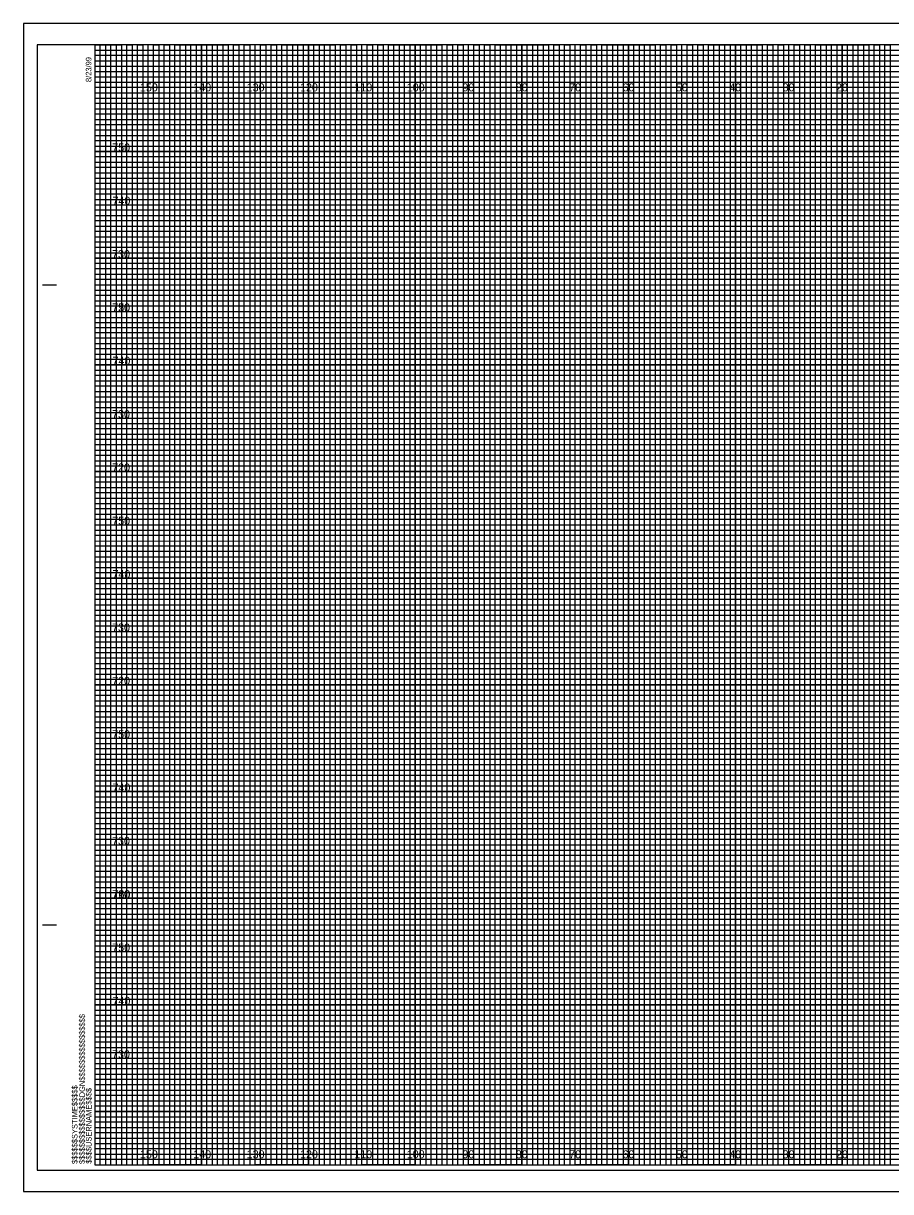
# Model space of a CAD drawing. Extents: x -13 to 323, y -5 to 214.
# Drawn here: x -13.4 to 149.1, y -5 to 214 of the extents above; entities that cross this region are included whole.
import ezdxf

# ---------------------------------------------------------------- set-up
doc = ezdxf.new("R2010")
doc.units = 0
for name, color, linetype in [('Prop XS Elevation Labels', 7, 'Continuous'), ('Prop XS Offset Labels', 7, 'Continuous'), ('Sheet Cross Section CELL', 7, 'Continuous'), ('Sheet Cross Section Grid Major CELL', 7, 'Continuous'), ('Sheet Cross Section Grid Middle CELL', 7, 'Continuous'), ('Sheet Cross Section Grid Minor 1 CELL', 7, 'Continuous'), ('Sheet Cross Section Grid Minor 2 CELL', 7, 'Continuous'), ('Sheet Cutting Line CELL', 7, 'Continuous'), ('Sheet DOT Grid CELL', 7, 'Continuous'), ('Sheet Plot Border Inside CELL', 7, 'Continuous'), ('Sheet Plot Border Outside CELL', 7, 'Continuous')]:
    doc.layers.add(name, color=color, linetype=linetype)

msp = doc.modelspace()

# ---------------------------------------------------------------- linework, layer by layer
at = {"layer": 'Sheet Cross Section CELL'}
for p, q in [((-9.8, 165), (-7.3, 165)), ((-9.7, 165), (-7.2, 165)), ((-9.8, 45), (-7.3, 45)), ((-9.7, 45), (-7.2, 45)), ((0, 0), (0, 0)), ((0, 0), (0, 0)), ((0, 0), (0, 0)), ((0, 0), (0, 0)), ((0, 0), (0, 0)), ((0, 0), (0, 0)), ((0, 0), (0, 0))]:
    msp.add_line(p, q, dxfattribs=at)
msp.add_lwpolyline([(320, 210), (0, 210), (0, 0), (320, 0)], close=True, dxfattribs=at)
at = {"layer": 'Sheet Cross Section Grid Major CELL'}
for p, q in [((10, 210), (0, 210)), ((10, 0), (10, 210)), ((30, 210), (20, 210)), ((20, 210), (20, 0)), ((30, 0), (30, 210)), ((50, 210), (40, 210)), ((40, 210), (40, 0)), ((50, 0), (50, 210)), ((70, 210), (60, 210)), ((60, 210), (60, 0)), ((70, 0), (70, 210)), ((90, 210), (80, 210)), ((80, 210), (80, 0)), ((90, 0), (90, 210)), ((110, 210), (100, 210)), ((100, 210), (100, 0)), ((110, 0), (110, 210)), ((130, 210), (120, 210)), ((120, 210), (120, 0)), ((130, 0), (130, 210)), ((150, 210), (140, 210)), ((140, 210), (140, 0)), ((20, 0), (10, 0)), ((40, 0), (30, 0)), ((60, 0), (50, 0)), ((80, 0), (70, 0)), ((100, 0), (90, 0)), ((120, 0), (110, 0)), ((140, 0), (130, 0))]:
    msp.add_line(p, q, dxfattribs=at)
for points in [[(0, 200), (320, 200), (320, 190), (0, 190)], [(0, 180), (320, 180), (320, 170), (0, 170)], [(0, 160), (320, 160), (320, 150), (0, 150)], [(0, 140), (320, 140), (320, 130), (0, 130)], [(0, 120), (320, 120), (320, 110), (0, 110)], [(0, 100), (320, 100), (320, 90), (0, 90)], [(0, 80), (320, 80), (320, 70), (0, 70)], [(0, 60), (320, 60), (320, 50), (0, 50)], [(0, 40), (320, 40), (320, 30), (0, 30)], [(0, 20), (320, 20), (320, 10), (0, 10)]]:
    msp.add_lwpolyline(points, dxfattribs=at)
at = {"layer": 'Sheet Cross Section Grid Middle CELL'}
for points in [[(0, 210), (5, 210), (5, 0), (15, 0), (15, 210), (25, 210), (25, 0), (35, 0), (35, 210), (45, 210), (45, 0), (55, 0), (55, 210), (65, 210), (65, 0), (75, 0), (75, 210), (85, 210), (85, 0), (95, 0), (95, 210), (105, 210), (105, 0), (115, 0), (115, 210), (125, 210), (125, 0), (135, 0), (135, 210), (145, 210), (145, 0), (155, 0)], [(0, 205), (275, 205)], [(0, 185), (320, 185), (320, 195), (0, 195)], [(0, 165), (320, 165), (320, 175), (0, 175)], [(0, 145), (320, 145), (320, 155), (0, 155)], [(0, 125), (320, 125), (320, 135), (0, 135)], [(0, 105), (320, 105), (320, 115), (0, 115)], [(0, 85), (320, 85), (320, 95), (0, 95)], [(0, 65), (320, 65), (320, 75), (0, 75)], [(0, 45), (320, 45), (320, 55), (0, 55)], [(0, 25), (320, 25), (320, 35), (0, 35)], [(0, 5), (320, 5), (320, 15), (0, 15)]]:
    msp.add_lwpolyline(points, dxfattribs=at)
at = {"layer": 'Sheet Cross Section Grid Minor 1 CELL'}
for p, q in [((0, 209), (260, 209)), ((260, 207.98), (0, 207.98)), ((0, 207.98), (0, 207)), ((0, 207), (260, 207)), ((260, 205.89), (0, 205.89)), ((0, 205.89), (0, 204)), ((0, 204), (320, 204))]:
    msp.add_line(p, q, dxfattribs=at)
for points in [[(0, 203), (270, 203), (320, 203), (320, 202), (0, 202)], [(0, 201), (320, 201), (320, 199), (0, 199)], [(0, 198), (320, 198), (320, 197), (0, 196.98)], [(0, 196), (320, 196), (320, 194), (0, 194)], [(0, 193), (320, 193), (320, 192), (0, 192)], [(0, 191), (320, 191), (320, 189), (0, 189)], [(0, 188), (320, 188), (320, 187), (0, 187)], [(0, 186), (320, 186), (320, 184), (0, 184)], [(0, 183), (320, 183), (320, 182), (0, 182)], [(0, 181), (320, 181), (320, 179), (0, 179)], [(0, 178), (320, 178), (320, 177), (0, 177)], [(0, 176), (320, 176), (320, 173.95), (320, 173), (320, 172), (0, 172)], [(0, 174), (320, 174), (320, 173), (0, 173)], [(0, 171), (320, 171), (320, 169), (0, 169.03)], [(0, 169.03), (320, 169), (320, 168), (0, 168)], [(0, 167), (320, 167), (320, 166), (0, 166)], [(0, 164), (320, 164), (320, 163), (0, 163)], [(0, 162), (320, 162), (320, 161), (0, 161)], [(-0.07, 158.89), (320, 158.89), (320, 157.88), (-0.07, 157.88)], [(0, 157), (320, 157), (320, 156), (0, 156)], [(0, 154), (320, 154), (320, 153), (0, 153)], [(0, 152), (320, 152), (320, 151), (0, 151)], [(0, 149), (320, 149), (320, 148), (0, 148)], [(0, 147), (320, 147), (320, 146), (0, 146)], [(0, 144), (320, 144), (320, 143), (0, 143)], [(0, 142), (320, 142), (320, 141), (0, 141)], [(0, 139), (320, 139), (319.99, 137.98), (0, 138)], [(0, 137), (320, 137), (320, 136), (0, 136)], [(0, 134), (320, 134), (320, 133), (0, 133)], [(0, 132), (320, 132), (320, 131), (0, 131)], [(0, 129), (320, 129), (320, 128), (0, 128)], [(0, 127), (320, 127), (320, 126), (0, 126)], [(0, 124), (320, 124), (320, 123), (0, 123)], [(0, 122), (320, 122), (320, 121), (0, 121)], [(0, 119), (320, 119), (320, 118), (0, 118)], [(0, 116.99), (320.07, 116.91), (320, 116), (0, 116)], [(0, 114), (320, 114), (320, 113), (0, 113)], [(0, 112), (320, 112), (320, 111), (0, 111)], [(0, 109), (320, 109), (320, 108), (0, 108)], [(0, 107), (320, 107), (320, 106), (0, 106)], [(0, 104), (320, 104), (320, 103), (0, 103)], [(0, 102), (320, 102), (320, 101), (0, 101)], [(0, 99), (320, 99), (320, 98), (0, 98)], [(0, 97), (320, 97), (320, 96), (0, 96)], [(0, 94), (320, 94), (320, 93), (0, 93)], [(0, 92), (320, 92), (320, 91), (0, 91)], [(0, 89), (320, 89), (320, 88), (0, 88)], [(0, 87), (320, 87), (320, 86), (0, 86)], [(0, 84), (320, 84), (320, 83), (0, 83)], [(0, 82), (320, 82), (320, 81), (0, 81)], [(0, 79), (320, 79), (319.99, 77.98), (0, 78)], [(0, 77), (320, 77), (320, 76), (0, 76)], [(0, 74), (320, 74), (320, 73), (0, 73)], [(0, 72), (320, 72), (320, 71), (0, 71)], [(0, 69), (320, 69), (320, 68), (0, 68)], [(0, 67), (320, 67), (320, 66), (0, 66)], [(0, 64), (320, 64), (320, 63), (0, 63)], [(0, 62), (320, 62), (320, 61), (0, 61)], [(0, 59), (320, 59), (320, 58), (0, 58)], [(0, 56.99), (320.07, 56.91), (320, 56), (0, 56)], [(0, 54), (320, 54), (320, 53), (0, 53)], [(0, 52), (320, 52), (320, 51), (0, 51)], [(0, 49), (320, 49), (320, 48), (0, 48)], [(0, 47), (320, 47), (320, 46), (0, 46)], [(0, 44), (320, 44), (320, 43), (0, 43)], [(0, 42), (320, 42), (320, 41), (0, 41)], [(0, 39), (320, 39), (320, 38), (0, 38)], [(0, 37), (320, 37), (320, 36), (0, 36)], [(0, 34), (320, 34), (320, 33), (0, 33)], [(0, 32), (320, 32), (320, 31), (0, 31)], [(0, 29), (320, 29), (320, 28), (0, 28)], [(0, 27), (320, 27), (320, 26), (0, 26)], [(0, 24), (320, 24), (320, 23), (0, 23)], [(0, 22), (320, 22), (320, 21), (0, 21)], [(0, 19), (320, 19), (320, 18), (0, 18)], [(0, 17), (320, 17), (320, 16), (0, 16)], [(0, 14), (320, 14), (320, 13), (0, 13)], [(0, 12), (320, 12), (320, 11), (0, 11)], [(0, 9), (320, 9), (320, 8), (0, 8)], [(0, 7), (320, 7), (320, 6), (0, 6)], [(0, 4), (320, 4), (320, 3), (0, 3)], [(0, 2), (320, 2), (320, 1), (0, 1)]]:
    msp.add_lwpolyline(points, dxfattribs=at)
at = {"layer": 'Sheet Cross Section Grid Minor 2 CELL'}
for points in [[(0, 0), (1, 0), (1, 210), (2, 210), (2, 0)], [(2, 0), (3, 0), (3, 210), (4, 210), (4, 0)], [(5, 0), (6, 0), (6, 210), (7, 210), (7, 0)], [(7, 0), (8, 0), (8, 210), (9, 210), (9, 0)], [(10, 0), (11, 0), (11, 210), (12, 210), (12, 0)], [(12, 0), (13, 0), (13, 210), (14, 210), (14, 0)], [(15, 0), (16, 0), (16, 210), (17, 210), (17, 0)], [(17, 0), (18, 0), (18, 210), (19, 210), (19, 0)], [(20, 0), (21, 0), (21, 210), (22, 210), (22, 0)], [(22, 0), (23, 0), (23, 210), (24, 210), (24, 0)], [(25, 0), (26, 0), (26, 210), (27, 210), (27, 0)], [(27, 0), (28, 0), (28, 210), (29, 210), (29, 0)], [(30, 0), (31, 0), (31, 210), (32, 210), (32, 0)], [(32, 0), (33, 0), (33, 210), (34, 210), (34, 0)], [(35, 0), (36, 0), (36, 210), (37, 210), (37, 0)], [(37, 0), (38, 0), (38, 210), (39, 210), (39, 0)], [(40, 0), (41, 0), (41, 210), (42, 210), (42, 0)], [(42, 0), (43, 0), (43, 210), (44, 210), (44, 0)], [(45, 0), (46, 0), (46, 210), (47, 210), (47, 0)], [(47, 0), (48, 0), (48, 210), (49, 210), (49, 0)], [(50, 0), (51, 0), (51, 210), (52, 210), (52, 0)], [(52, 0), (53, 0), (53, 210), (54, 210), (54, 0)], [(55, 0), (56, 0), (56, 210), (57, 210), (57, 0)], [(57, 0), (58, 0), (58, 210), (59, 210), (59, 0)], [(60, 0), (61, 0), (61, 210), (62, 210), (62, 0)], [(62, 0), (63, 0), (63, 210), (64, 210), (64, 0)], [(65, 0), (66, 0), (66, 210), (67, 210), (67, 0)], [(67, 0), (68, 0), (68, 210), (69, 210), (69, 0)], [(70, 0), (71, 0), (71, 210), (72, 210), (72, 0)], [(72, 0), (73, 0), (73, 210), (74, 210), (74, 0)], [(75, 0), (76, 0), (76, 210), (77, 210), (77, 0)], [(77, 0), (78, 0), (78, 210), (79, 210), (79, 0)], [(80, 0), (81, 0), (81, 210), (82, 210), (82, 0)], [(82, 0), (83, 0), (83, 210), (84, 210), (84, 0)], [(85, 0), (86, 0), (86, 210), (87, 210), (87, 0)], [(87, 0), (88, 0), (88, 210), (89, 210), (89, 0)], [(90, 0), (91, 0), (91, 210), (92, 210), (92, 0)], [(92, 0), (93, 0), (93, 210), (94, 210), (94, 0)], [(95, 0), (96, 0), (96, 210), (97, 210), (97, 0)], [(97, 0), (98, 0), (98, 210), (99, 210), (99, 0)], [(100, 0), (101, 0), (101, 210), (102, 210), (102, 0)], [(102, 0), (103, 0), (103, 210), (104, 210), (104, 0)], [(105, 0), (106, 0), (106, 210), (107, 210), (107, 0)], [(107, 0), (108, 0), (108, 210), (109, 210), (109, 0)], [(110, 0), (111, 0), (111, 210), (112, 210), (112, 0)], [(112, 0), (113, 0), (113, 210), (114, 210), (114, 0)], [(115, 0), (116, 0), (116, 210), (117, 210), (117, 0)], [(117, 0), (118, 0), (118, 210), (119, 210), (119, 0)], [(120, 0), (121, 0), (121, 210), (122, 210), (122, 0)], [(122, 0), (123, 0), (123, 210), (124, 210), (124, 0)], [(125, 0), (126, 0), (126, 210), (127, 210), (127, 0)], [(127, 0), (128, 0), (128, 210), (129, 210), (129, 0)], [(130, 0), (131, 0), (131, 210), (132, 210), (132, 0)], [(132, 0), (133, 0), (133, 210), (134, 210), (134, 0)], [(135, 0), (136, 0), (136, 210), (137, 210), (137, 0)], [(137, 0), (138, 0), (138, 210), (139, 210), (139, 0)], [(140, 0), (141, 0), (141, 210), (142, 210), (142, 0)], [(142, 0), (143, 0), (143, 210), (144, 210), (144, 0)], [(145, 0), (146, 0), (146, 210), (147, 210), (147, 0)], [(147, 0), (148, 0), (148, 210), (149, 210), (149, 0)]]:
    msp.add_lwpolyline(points, dxfattribs=at)
at = {"layer": 'Sheet Cutting Line CELL'}
for p, q in [((323.3, 214), (-13.4, 214)), ((-13.4, 214), (-13.4, -5)), ((-13.4, -5), (323.3, -5))]:
    msp.add_line(p, q, dxfattribs=at)
at = {"layer": 'Sheet DOT Grid CELL'}
for p, q in [((10, 0), (10, 210)), ((20, 0), (20, 210)), ((30, 0), (30, 210)), ((40, 0), (40, 210)), ((50, 0), (50, 210)), ((60, 0), (60, 210)), ((70, 0), (70, 210)), ((80, 0), (80, 210)), ((90, 0), (90, 210)), ((100, 0), (100, 210)), ((110, 0), (110, 210)), ((120, 0), (120, 210)), ((130, 0), (130, 210)), ((140, 0), (140, 210)), ((0, 200), (320, 200)), ((0, 190), (320, 190)), ((0, 180), (320, 180)), ((0, 170), (320, 170)), ((0, 160), (320, 160)), ((0, 150), (320, 150)), ((0, 140), (320, 140)), ((0, 130), (320, 130)), ((0, 120), (320, 120)), ((0, 110), (320, 110)), ((0, 100), (320, 100)), ((0, 90), (320, 90)), ((0, 80), (320, 80)), ((0, 70), (320, 70)), ((0, 60), (320, 60)), ((0, 50), (320, 50)), ((0, 40), (320, 40)), ((0, 30), (320, 30)), ((0, 20), (320, 20)), ((0, 10), (320, 10))]:
    msp.add_line(p, q, dxfattribs=at)
at = {"layer": 'Sheet Plot Border Inside CELL'}
msp.add_lwpolyline([(-10.8, -1), (322.4, -1), (322.4, 210), (-10.8, 210)], close=True, dxfattribs=at)
at = {"layer": 'Sheet Plot Border Outside CELL'}
msp.add_lwpolyline([(-13.4, -5), (323.3, -5), (323.3, 214), (-13.4, 214)], close=True, dxfattribs=at)

# ---------------------------------------------------------------- texts
at = {"layer": 'Prop XS Elevation Labels'}
for s, p in [('750', (3.25, 190)), ('740', (3.3, 180)), ('730', (3.22, 170)), ('720', (3.23, 160)), ('750', (3.25, 160)), ('740', (3.3, 150)), ('730', (3.22, 140)), ('720', (3.23, 130)), ('750', (3.25, 120)), ('740', (3.3, 110)), ('730', (3.22, 100)), ('720', (3.23, 90)), ('750', (3.25, 80)), ('740', (3.3, 70)), ('730', (3.22, 60)), ('720', (3.23, 50)), ('760', (3.3, 50)), ('750', (3.25, 40)), ('740', (3.3, 30)), ('730', (3.22, 20))]:
    msp.add_text(s, height=1.5, dxfattribs=at).set_placement(p)
at = {"layer": 'Prop XS Offset Labels'}
for s, p in [('150', (8.44, 201.25)), ('140', (18.44, 201.25)), ('130', (28.44, 201.25)), ('120', (38.44, 201.25)), ('110', (48.62, 201.25)), ('100', (58.44, 201.25)), ('90', (68.86, 201.25)), ('80', (78.86, 201.25)), ('70', (88.86, 201.25)), ('60', (98.86, 201.25)), ('50', (108.86, 201.25)), ('40', (118.86, 201.25)), ('30', (128.86, 201.25)), ('20', (138.86, 201.25)), ('150', (8.44, 1.25)), ('140', (18.44, 1.25)), ('130', (28.44, 1.25)), ('120', (38.44, 1.25)), ('110', (48.62, 1.25)), ('100', (58.44, 1.25)), ('90', (68.86, 1.25)), ('80', (78.86, 1.25)), ('70', (88.86, 1.25)), ('60', (98.86, 1.25)), ('50', (108.86, 1.25)), ('40', (118.86, 1.25)), ('30', (128.86, 1.25)), ('20', (138.86, 1.25))]:
    msp.add_text(s, height=1.5, dxfattribs=at).set_placement(p)
at = {"layer": 'Sheet Cross Section CELL'}
for s, p in [('8/23/99', (-0.65, 203)), ('$$$$$$$$$$$$$$$$DGN$$$$$$$$$$$$$$$$', (-1.88, 0.18)), ('$$$$$$SYSTIME$$$$$', (-3.26, 0.18)), ('$$$$USERNAME$$$$', (-0.62, 0.23))]:
    msp.add_text(s, height=1.05, rotation=90, dxfattribs=at).set_placement(p)

doc.saveas('drawing.dxf')
